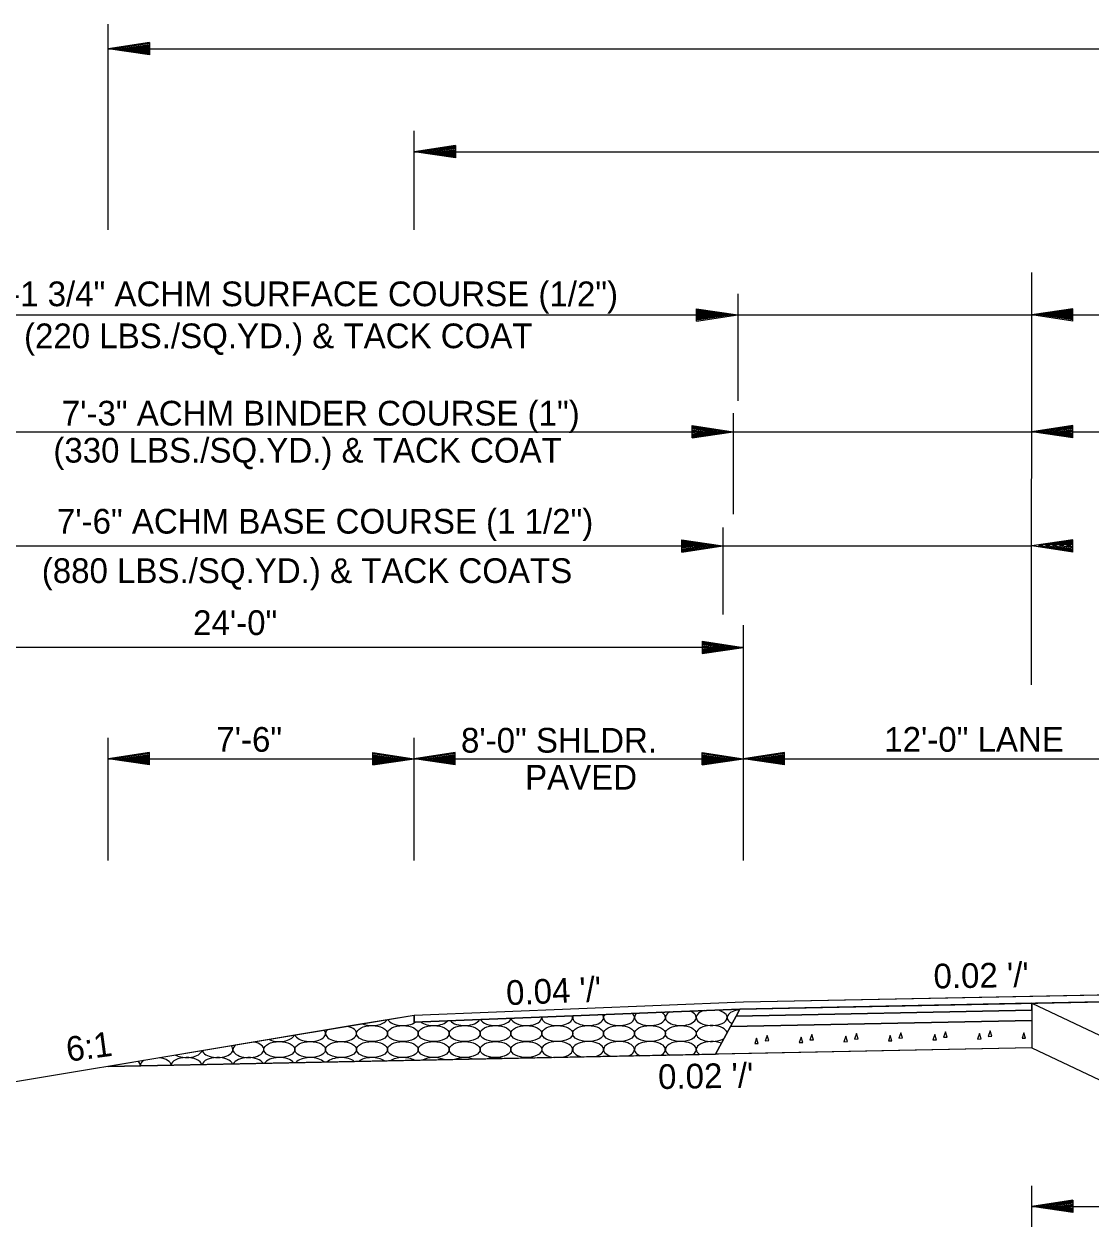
# Model space of a CAD drawing. Extents: x 1371763 to 1372860, y 385599 to 385872.
# Drawn here: x 1372047.92 to 1372073.83, y 385772.99 to 385802.2 of the extents above; entities that cross this region are included whole.
import ezdxf

# ---------------------------------------------------------------- set-up
doc = ezdxf.new("R2010")
doc.units = 0
doc.layers.add('R_Draft', color=7, linetype='Continuous')

msp = doc.modelspace()

# ---------------------------------------------------------------- linework, layer by layer
at = {"layer": 'R_Draft'}
for p, q in [((1372049.964, 385797.204), (1372049.964, 385802.202)), ((1372050.964, 385801.752), (1372049.964, 385801.602)), ((1372050.964, 385801.727), (1372050.131, 385801.602)), ((1372050.964, 385801.701), (1372050.303, 385801.602)), ((1372050.964, 385801.676), (1372050.469, 385801.602)), ((1372050.964, 385801.65), (1372050.639, 385801.602)), ((1372050.964, 385801.625), (1372050.806, 385801.602)), ((1372050.964, 385801.752), (1372050.964, 385801.452)), ((1372049.964, 385801.602), (1372116.827, 385801.602)), ((1372050.964, 385801.452), (1372049.964, 385801.602)), ((1372050.964, 385801.477), (1372050.131, 385801.602)), ((1372050.964, 385801.502), (1372050.303, 385801.602)), ((1372050.964, 385801.527), (1372050.469, 385801.602)), ((1372050.964, 385801.553), (1372050.639, 385801.602)), ((1372050.964, 385801.578), (1372050.806, 385801.602)), ((1372057.395, 385797.204), (1372057.395, 385799.612)), ((1372058.395, 385799.252), (1372057.395, 385799.102)), ((1372057.395, 385799.102), (1372109.395, 385799.102)), ((1372058.395, 385798.952), (1372057.395, 385799.102)), ((1372058.395, 385799.227), (1372057.562, 385799.102)), ((1372058.395, 385798.977), (1372057.562, 385799.102)), ((1372058.395, 385799.201), (1372057.734, 385799.102)), ((1372058.395, 385799.002), (1372057.734, 385799.102)), ((1372058.395, 385799.176), (1372057.901, 385799.102)), ((1372058.395, 385799.027), (1372057.901, 385799.102)), ((1372058.395, 385799.15), (1372058.07, 385799.102)), ((1372058.395, 385799.053), (1372058.07, 385799.102)), ((1372058.395, 385799.125), (1372058.237, 385799.102)), ((1372058.395, 385799.078), (1372058.237, 385799.102)), ((1372058.395, 385799.252), (1372058.395, 385798.952)), ((1372072.394, 385786.157), (1372072.395, 385796.171)), ((1372065.254, 385795.649), (1372065.254, 385793.051)), ((1372064.254, 385795.289), (1372065.254, 385795.139)), ((1372064.254, 385794.989), (1372064.254, 385795.289)), ((1372064.254, 385795.264), (1372065.087, 385795.139)), ((1372064.254, 385795.239), (1372064.915, 385795.139)), ((1372064.254, 385795.214), (1372064.749, 385795.139)), ((1372064.254, 385795.188), (1372064.579, 385795.139)), ((1372073.395, 385795.289), (1372072.395, 385795.139)), ((1372073.395, 385795.264), (1372072.562, 385795.139)), ((1372073.395, 385795.239), (1372072.734, 385795.139)), ((1372073.395, 385795.214), (1372072.901, 385795.139)), ((1372073.395, 385795.188), (1372073.07, 385795.139)), ((1372073.395, 385794.989), (1372073.395, 385795.289)), ((1372046.72, 385795.139), (1372072.395, 385795.139)), ((1372064.254, 385795.163), (1372064.412, 385795.139)), ((1372064.254, 385794.989), (1372065.254, 385795.139)), ((1372064.254, 385795.091), (1372064.579, 385795.139)), ((1372064.254, 385795.04), (1372064.915, 385795.139)), ((1372064.254, 385795.014), (1372065.087, 385795.139)), ((1372064.254, 385795.065), (1372064.749, 385795.139)), ((1372064.254, 385795.116), (1372064.412, 385795.139)), ((1372072.395, 385795.139), (1372094.395, 385795.14)), ((1372073.395, 385794.989), (1372072.395, 385795.139)), ((1372073.395, 385795.014), (1372072.562, 385795.139)), ((1372073.395, 385795.04), (1372072.734, 385795.139)), ((1372073.395, 385795.065), (1372072.901, 385795.139)), ((1372073.395, 385795.091), (1372073.07, 385795.139)), ((1372073.395, 385795.163), (1372073.237, 385795.139)), ((1372073.395, 385795.116), (1372073.237, 385795.139)), ((1372065.144, 385792.751), (1372065.144, 385790.3)), ((1372047.354, 385792.301), (1372072.395, 385792.301)), ((1372064.144, 385792.451), (1372065.144, 385792.301)), ((1372064.144, 385792.151), (1372064.144, 385792.451)), ((1372064.144, 385792.426), (1372064.977, 385792.301)), ((1372064.144, 385792.401), (1372064.805, 385792.301)), ((1372064.144, 385792.376), (1372064.639, 385792.301)), ((1372064.144, 385792.35), (1372064.469, 385792.301)), ((1372064.144, 385792.325), (1372064.302, 385792.301)), ((1372064.144, 385792.151), (1372065.144, 385792.301)), ((1372064.144, 385792.253), (1372064.469, 385792.301)), ((1372064.144, 385792.202), (1372064.805, 385792.301)), ((1372064.144, 385792.176), (1372064.977, 385792.301)), ((1372064.144, 385792.227), (1372064.639, 385792.301)), ((1372064.144, 385792.278), (1372064.302, 385792.301)), ((1372073.395, 385792.451), (1372072.395, 385792.301)), ((1372073.395, 385792.151), (1372072.395, 385792.301)), ((1372072.395, 385792.301), (1372094.395, 385792.301)), ((1372073.395, 385792.426), (1372072.562, 385792.301)), ((1372073.395, 385792.176), (1372072.562, 385792.301)), ((1372073.395, 385792.401), (1372072.734, 385792.301)), ((1372073.395, 385792.202), (1372072.734, 385792.301)), ((1372073.395, 385792.376), (1372072.901, 385792.301)), ((1372073.395, 385792.227), (1372072.901, 385792.301)), ((1372073.395, 385792.35), (1372073.07, 385792.301)), ((1372073.395, 385792.253), (1372073.07, 385792.301)), ((1372073.395, 385792.325), (1372073.237, 385792.301)), ((1372073.395, 385792.278), (1372073.237, 385792.301)), ((1372073.395, 385792.151), (1372073.395, 385792.451)), ((1372064.895, 385789.976), (1372064.895, 385787.861)), ((1372063.895, 385789.676), (1372064.895, 385789.526)), ((1372063.895, 385789.376), (1372063.895, 385789.676)), ((1372063.895, 385789.651), (1372064.728, 385789.526)), ((1372073.395, 385789.676), (1372072.395, 385789.526)), ((1372073.395, 385789.651), (1372072.562, 385789.526)), ((1372073.395, 385789.376), (1372073.395, 385789.676)), ((1372047.354, 385789.526), (1372072.395, 385789.526)), ((1372063.895, 385789.626), (1372064.556, 385789.526)), ((1372063.895, 385789.601), (1372064.39, 385789.526)), ((1372063.895, 385789.575), (1372064.22, 385789.526)), ((1372063.895, 385789.55), (1372064.053, 385789.526)), ((1372063.895, 385789.376), (1372064.895, 385789.526)), ((1372063.895, 385789.478), (1372064.22, 385789.526)), ((1372063.895, 385789.427), (1372064.556, 385789.526)), ((1372063.895, 385789.401), (1372064.728, 385789.526)), ((1372063.895, 385789.452), (1372064.39, 385789.526)), ((1372063.895, 385789.503), (1372064.053, 385789.526)), ((1372073.395, 385789.376), (1372072.395, 385789.526)), ((1372073.395, 385789.401), (1372072.562, 385789.526)), ((1372073.395, 385789.626), (1372072.734, 385789.526)), ((1372073.395, 385789.427), (1372072.734, 385789.526)), ((1372073.395, 385789.601), (1372072.9, 385789.526)), ((1372073.395, 385789.452), (1372072.9, 385789.526)), ((1372073.395, 385789.575), (1372073.07, 385789.526)), ((1372073.395, 385789.478), (1372073.07, 385789.526)), ((1372073.395, 385789.55), (1372073.237, 385789.526)), ((1372073.395, 385789.503), (1372073.237, 385789.526)), ((1372065.392, 385781.89), (1372065.393, 385787.604)), ((1372065.393, 385787.063), (1372041.393, 385787.063)), ((1372064.393, 385787.213), (1372065.393, 385787.063)), ((1372064.393, 385787.213), (1372064.393, 385786.913)), ((1372064.393, 385787.188), (1372065.226, 385787.063)), ((1372064.393, 385787.163), (1372065.054, 385787.063)), ((1372064.393, 385787.138), (1372064.887, 385787.063)), ((1372064.393, 385787.112), (1372064.718, 385787.063)), ((1372064.393, 385787.087), (1372064.551, 385787.063)), ((1372064.393, 385786.913), (1372065.393, 385787.063)), ((1372064.393, 385787.014), (1372064.718, 385787.063)), ((1372064.393, 385786.964), (1372065.054, 385787.063)), ((1372064.393, 385786.938), (1372065.226, 385787.063)), ((1372064.393, 385786.989), (1372064.887, 385787.063)), ((1372064.393, 385787.04), (1372064.551, 385787.063)), ((1372049.963, 385781.89), (1372049.964, 385784.864)), ((1372057.392, 385781.89), (1372057.393, 385784.864)), ((1372050.964, 385784.507), (1372049.964, 385784.357)), ((1372050.964, 385784.482), (1372050.131, 385784.357)), ((1372050.964, 385784.456), (1372050.303, 385784.357)), ((1372050.964, 385784.431), (1372050.469, 385784.357)), ((1372050.964, 385784.406), (1372050.639, 385784.357)), ((1372050.964, 385784.38), (1372050.806, 385784.357)), ((1372050.964, 385784.207), (1372050.964, 385784.507)), ((1372056.393, 385784.507), (1372057.393, 385784.357)), ((1372056.393, 385784.207), (1372056.393, 385784.507)), ((1372056.393, 385784.482), (1372057.226, 385784.357)), ((1372056.393, 385784.456), (1372057.054, 385784.357)), ((1372056.393, 385784.431), (1372056.887, 385784.357)), ((1372056.393, 385784.406), (1372056.718, 385784.357)), ((1372056.393, 385784.38), (1372056.551, 385784.357)), ((1372058.393, 385784.507), (1372057.393, 385784.357)), ((1372058.393, 385784.482), (1372057.56, 385784.357)), ((1372058.393, 385784.456), (1372057.732, 385784.357)), ((1372058.393, 385784.431), (1372057.898, 385784.357)), ((1372058.393, 385784.406), (1372058.068, 385784.357)), ((1372058.393, 385784.38), (1372058.235, 385784.357)), ((1372058.393, 385784.207), (1372058.393, 385784.507)), ((1372064.393, 385784.507), (1372065.393, 385784.357)), ((1372064.393, 385784.207), (1372064.393, 385784.507)), ((1372064.393, 385784.482), (1372065.226, 385784.357)), ((1372064.393, 385784.456), (1372065.054, 385784.357)), ((1372064.393, 385784.431), (1372064.887, 385784.357)), ((1372064.393, 385784.406), (1372064.718, 385784.357)), ((1372064.393, 385784.38), (1372064.551, 385784.357)), ((1372066.393, 385784.507), (1372065.393, 385784.357)), ((1372066.393, 385784.482), (1372065.56, 385784.357)), ((1372066.393, 385784.456), (1372065.732, 385784.357)), ((1372066.393, 385784.431), (1372065.898, 385784.357)), ((1372066.393, 385784.406), (1372066.068, 385784.357)), ((1372066.393, 385784.38), (1372066.235, 385784.357)), ((1372066.393, 385784.207), (1372066.393, 385784.507)), ((1372049.964, 385784.357), (1372057.393, 385784.357)), ((1372050.964, 385784.207), (1372049.964, 385784.357)), ((1372050.964, 385784.232), (1372050.131, 385784.357)), ((1372050.964, 385784.257), (1372050.303, 385784.357)), ((1372050.964, 385784.282), (1372050.469, 385784.357)), ((1372050.964, 385784.308), (1372050.639, 385784.357)), ((1372050.964, 385784.333), (1372050.806, 385784.357)), ((1372056.393, 385784.207), (1372057.393, 385784.357)), ((1372056.393, 385784.308), (1372056.718, 385784.357)), ((1372056.393, 385784.257), (1372057.054, 385784.357)), ((1372056.393, 385784.232), (1372057.226, 385784.357)), ((1372056.393, 385784.282), (1372056.887, 385784.357)), ((1372056.393, 385784.333), (1372056.551, 385784.357)), ((1372057.393, 385784.357), (1372065.393, 385784.357)), ((1372058.393, 385784.207), (1372057.393, 385784.357)), ((1372058.393, 385784.232), (1372057.56, 385784.357)), ((1372058.393, 385784.257), (1372057.732, 385784.357)), ((1372058.393, 385784.282), (1372057.898, 385784.357)), ((1372058.393, 385784.308), (1372058.068, 385784.357)), ((1372058.393, 385784.333), (1372058.235, 385784.357)), ((1372064.393, 385784.207), (1372065.393, 385784.357)), ((1372064.393, 385784.308), (1372064.718, 385784.357)), ((1372064.393, 385784.257), (1372065.054, 385784.357)), ((1372064.393, 385784.232), (1372065.226, 385784.357)), ((1372064.393, 385784.282), (1372064.887, 385784.357)), ((1372064.393, 385784.333), (1372064.551, 385784.357)), ((1372065.393, 385784.357), (1372077.393, 385784.357)), ((1372066.393, 385784.207), (1372065.393, 385784.357)), ((1372066.393, 385784.232), (1372065.56, 385784.357)), ((1372066.393, 385784.257), (1372065.732, 385784.357)), ((1372066.393, 385784.282), (1372065.898, 385784.357)), ((1372066.393, 385784.308), (1372066.068, 385784.357)), ((1372066.393, 385784.333), (1372066.235, 385784.357)), ((1372083.395, 385778.639), (1372065.305, 385778.277)), ((1372083.395, 385778.806), (1372065.395, 385778.446)), ((1372065.395, 385778.446), (1372057.395, 385778.126)), ((1372065.305, 385778.277), (1372057.395, 385777.961)), ((1372065.305, 385778.277), (1372065.214, 385778.109)), ((1372072.396, 385778.419), (1372074.884, 385777.247)), ((1372057.395, 385778.126), (1372041.395, 385775.459)), ((1372057.395, 385778.126), (1372057.395, 385777.961)), ((1372065.214, 385778.109), (1372065.077, 385777.856)), ((1372072.395, 385778.002), (1372065.077, 385777.856)), ((1372065.077, 385777.856), (1372064.713, 385777.182)), ((1372072.395, 385777.336), (1372049.964, 385776.887)), ((1372072.395, 385777.336), (1372074.883, 385776.164)), ((1372072.395, 385772.987), (1372072.395, 385773.987)), ((1372073.395, 385773.637), (1372072.395, 385773.487)), ((1372073.395, 385773.612), (1372072.562, 385773.487)), ((1372073.395, 385773.586), (1372072.734, 385773.487)), ((1372073.395, 385773.561), (1372072.901, 385773.487)), ((1372073.395, 385773.637), (1372073.395, 385773.337)), ((1372073.395, 385773.337), (1372072.395, 385773.487)), ((1372072.395, 385773.487), (1372094.395, 385773.487)), ((1372073.395, 385773.362), (1372072.562, 385773.487)), ((1372073.395, 385773.387), (1372072.734, 385773.487)), ((1372073.395, 385773.412), (1372072.901, 385773.487)), ((1372073.395, 385773.535), (1372073.07, 385773.487)), ((1372073.395, 385773.438), (1372073.07, 385773.487)), ((1372073.395, 385773.51), (1372073.237, 385773.487)), ((1372073.395, 385773.463), (1372073.237, 385773.487))]:
    msp.add_line(p, q, dxfattribs=at)
for points in [[(1372083.395, 385778.806), (1372065.395, 385778.446), (1372057.395, 385778.126), (1372057.395, 385777.961), (1372065.305, 385778.277), (1372083.395, 385778.639), (1372094.395, 385778.419), (1372101.486, 385778.277), (1372109.395, 385777.961), (1372109.395, 385778.126), (1372101.395, 385778.446)], [(1372049.964, 385776.887), (1372064.713, 385777.182), (1372065.077, 385777.856), (1372065.214, 385778.109), (1372065.305, 385778.277), (1372057.395, 385777.961), (1372057.395, 385778.126), (1372056.094, 385777.909)], [(1372072.395, 385778.002), (1372065.077, 385777.856), (1372065.214, 385778.109), (1372072.395, 385778.252)], [(1372072.396, 385778.419), (1372065.305, 385778.277), (1372065.214, 385778.109), (1372072.395, 385778.252)], [(1372072.395, 385777.336), (1372064.713, 385777.182), (1372065.077, 385777.856), (1372072.395, 385778.002)]]:
    msp.add_lwpolyline(points, close=True, dxfattribs=at)
for points in [[(1372072.395, 385778.252), (1372065.214, 385778.109)], [(1372072.396, 385778.419), (1372072.395, 385778.252), (1372072.395, 385778.002), (1372072.395, 385777.336)], [(1372067.055, 385777.662), (1372067.007, 385777.529), (1372067.095, 385777.533), (1372067.055, 385777.662)], [(1372068.138, 385777.683), (1372068.089, 385777.551), (1372068.177, 385777.554), (1372068.138, 385777.683)], [(1372069.22, 385777.705), (1372069.172, 385777.572), (1372069.26, 385777.576), (1372069.22, 385777.705)], [(1372070.043, 385777.661), (1372069.995, 385777.528), (1372070.083, 385777.532), (1372070.043, 385777.661)], [(1372070.302, 385777.727), (1372070.254, 385777.594), (1372070.342, 385777.598), (1372070.302, 385777.727)], [(1372071.126, 385777.682), (1372071.077, 385777.55), (1372071.165, 385777.553), (1372071.126, 385777.682)], [(1372071.385, 385777.748), (1372071.336, 385777.616), (1372071.424, 385777.619), (1372071.385, 385777.748)], [(1372072.208, 385777.704), (1372072.16, 385777.571), (1372072.248, 385777.575), (1372072.208, 385777.704)], [(1372065.714, 385777.574), (1372065.666, 385777.441), (1372065.754, 385777.445), (1372065.714, 385777.574)], [(1372065.973, 385777.64), (1372065.925, 385777.507), (1372066.013, 385777.511), (1372065.973, 385777.64)], [(1372066.796, 385777.596), (1372066.748, 385777.463), (1372066.836, 385777.467), (1372066.796, 385777.596)], [(1372067.879, 385777.618), (1372067.83, 385777.485), (1372067.918, 385777.488), (1372067.879, 385777.618)], [(1372068.961, 385777.639), (1372068.913, 385777.506), (1372069.001, 385777.51), (1372068.961, 385777.639)]]:
    msp.add_lwpolyline(points, dxfattribs=at)
for centre, start_param, end_param in [((1372064.622, 385778.072), 2.071165, 7.507767), ((1372065.372, 385778.072), 1.772656, 3.965142), ((1372065.372, 385778.461), 4.408497, 4.521498), ((1372056.369, 385778.072), 4.067558, 5.979925), ((1372057.119, 385778.072), 3.416887, 5.680767), ((1372057.869, 385778.072), 3.712943, 5.865997), ((1372058.619, 385778.072), 3.544798, 6.034142), ((1372059.37, 385778.072), 3.38581, 6.19313), ((1372060.12, 385778.072), 3.231019, 6.347921), ((1372060.87, 385778.072), 3.076526, 6.502414), ((1372061.62, 385778.072), 2.918502, 6.660437), ((1372062.371, 385778.072), 2.752246, 6.826694), ((1372063.121, 385778.072), 2.570523, 7.008416), ((1372063.871, 385778.072), 2.358849, 7.220088), ((1372054.868, 385777.684), 3.350954, 6.696528), ((1372055.618, 385777.684), 2.657027, 7.390455), ((1372064.622, 385777.684), 0.102318, 5.635481), ((1372065.372, 385777.684), 2.774996, 2.962802), ((1372052.617, 385777.295), 3.284573, 6.762909), ((1372053.368, 385777.295), 2.557848, 7.489634), ((1372054.118, 385777.684), 3.989151, 6.058331), ((1372060.87, 385777.295), 4.966385, 10.818776), ((1372061.62, 385777.295), 5.202674, 10.582487), ((1372062.371, 385777.295), 5.355933, 10.429228), ((1372063.121, 385777.295), 5.480718, 10.304443), ((1372063.871, 385777.295), 5.590031, 10.195131), ((1372064.622, 385777.295), 0.895461, 3.812485), ((1372051.117, 385776.906), 0.056891, 1.319853), ((1372051.867, 385776.906), 0.134215, 3.084576), ((1372051.867, 385777.295), 3.914247, 6.133235), ((1372052.617, 385776.906), 0.212118, 3.006673), ((1372053.368, 385776.906), 0.291102, 2.927689), ((1372054.118, 385776.906), 0.371734, 2.847057), ((1372054.868, 385776.906), 0.454688, 2.764103), ((1372055.618, 385776.906), 0.540811, 2.67798), ((1372056.369, 385776.906), 0.631229, 2.587562), ((1372057.119, 385776.906), 0.727545, 2.491246), ((1372057.869, 385776.906), 0.832228, 2.386563), ((1372058.619, 385776.906), 0.949541, 2.26925), ((1372059.37, 385776.906), 1.088272, 2.130518), ((1372060.12, 385776.906), 1.274485, 1.944306), ((1372049.616, 385776.906), 6.185294, 6.205443), ((1372050.366, 385776.906), 3.217433, 3.239114), ((1372050.366, 385776.906), 6.262862, 6.83005), ((1372051.117, 385776.906), 2.444445, 3.1619)]:
    msp.add_ellipse(centre, major_axis=(0.375, 0), ratio=0.517889, start_param=start_param, end_param=end_param, dxfattribs=at)
for centre in [(1372056.369, 385777.684), (1372057.119, 385777.684), (1372057.869, 385777.684), (1372058.619, 385777.684), (1372059.37, 385777.684), (1372060.12, 385777.684), (1372060.87, 385777.684), (1372061.62, 385777.684), (1372062.371, 385777.684), (1372063.121, 385777.684), (1372063.871, 385777.684), (1372054.118, 385777.295), (1372054.868, 385777.295), (1372055.618, 385777.295), (1372056.369, 385777.295), (1372057.119, 385777.295), (1372057.869, 385777.295), (1372058.619, 385777.295), (1372059.37, 385777.295), (1372060.12, 385777.295)]:
    msp.add_ellipse(centre, major_axis=(0.375, 0), ratio=0.517889, dxfattribs=at)

# ---------------------------------------------------------------- texts
for s, rotation, p in [('7\'-1 3/4" ACHM SURFACE COURSE (1/2")', 360, (1372046.956, 385795.349)), ('(220 LBS./SQ.YD.) & TACK COAT', 360, (1372047.918, 385794.329)), ('7\'-3" ACHM BINDER COURSE (1")', 360, (1372048.835, 385792.451)), ('(330 LBS./SQ.YD.) & TACK COAT', 360, (1372048.63, 385791.551)), ('7\'-6" ACHM BASE COURSE (1 1/2")', 360, (1372048.717, 385789.826)), ('(880 LBS./SQ.YD.) & TACK COATS', 360, (1372048.349, 385788.626)), ('24\'-0"', 360, (1372052.025, 385787.363)), ('7\'-6"', 360, (1372052.589, 385784.528)), ('8\'-0" SHLDR.', 360, (1372058.532, 385784.507)), ('12\'-0" LANE', 360, (1372068.814, 385784.528)), ('PAVED', 360, (1372060.089, 385783.607)), ("0.02 '/'", 0.9853, (1372070.015, 385778.777)), ("0.04 '/'", 2.3777, (1372059.64, 385778.372)), ('6:1', 7.7154, (1372048.983, 385776.997)), ("0.02 '/'", 0.9853, (1372063.325, 385776.335))]:
    msp.add_text(s, height=0.6, rotation=rotation, dxfattribs=at).set_placement(p)

doc.saveas('drawing.dxf')
